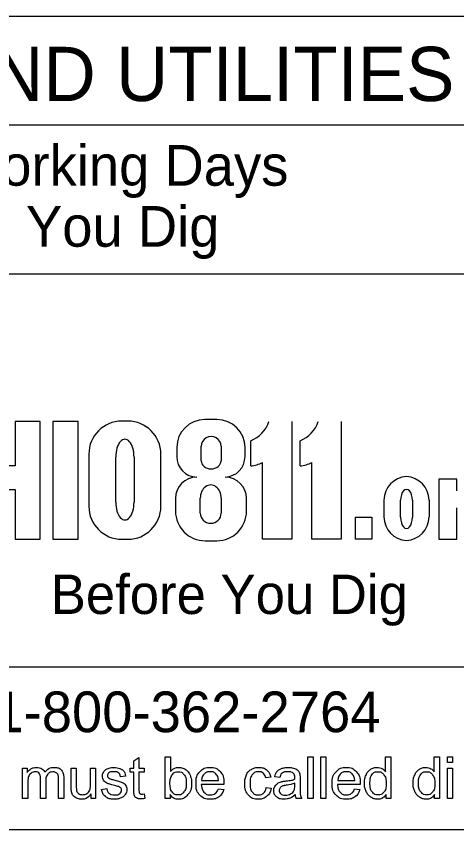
# Model space of a CAD drawing. Extents: x 421.3 to 469.3, y 221.6 to 248.2.
# Drawn here: x 426.536 to 428.323, y 223.579 to 226.879 of the extents above; entities that cross this region are included whole.
import ezdxf

# ---------------------------------------------------------------- set-up
doc = ezdxf.new("R2010")
doc.units = 0
doc.layers.add('SH_Data', color=7, linetype='Continuous')

msp = doc.modelspace()

# ---------------------------------------------------------------- linework, layer by layer
at = {"layer": 'SH_Data'}
for p, q in [((424.3328, 226.8787), (429.5577, 226.8787)), ((424.3328, 226.4387), (429.5577, 226.4387)), ((424.3328, 225.8337), (429.5577, 225.8337)), ((426.9891, 225.2364), (426.9644, 225.2364)), ((427.3503, 225.2429), (427.3014, 225.2429)), ((427.654, 225.2349), (427.654, 224.7569)), ((427.8541, 225.2349), (427.8541, 224.7569)), ((427.1874, 225.1289), (427.1874, 225.0926)), ((427.2862, 225.0756), (427.2862, 225.1343)), ((427.3671, 225.1343), (427.3671, 225.0756)), ((427.4643, 225.0926), (427.4643, 225.1289)), ((427.4873, 225.0546), (427.4873, 225.1564)), ((427.6874, 225.0546), (427.6874, 225.1564)), ((426.8308, 225.1027), (426.8308, 224.8906)), ((427.1228, 224.8906), (427.1228, 225.1027)), ((426.9397, 224.9076), (426.9397, 225.0903)), ((427.0141, 225.0903), (427.0141, 224.9076)), ((427.5356, 224.7569), (427.5356, 225.0686)), ((427.7357, 224.7569), (427.7357, 225.0686)), ((428.3228, 225.0004), (428.2498, 225.0004)), ((428.2498, 225.0004), (428.2498, 224.7569)), ((428.3228, 224.9533), (428.3228, 225.0004)), ((427.1818, 224.9225), (427.1818, 224.8717)), ((427.2827, 224.8628), (427.2827, 224.9239)), ((427.3676, 224.9239), (427.3676, 224.8628)), ((427.4703, 224.8717), (427.4703, 224.9225)), ((428.0279, 224.8478), (428.0279, 224.9156)), ((428.0951, 224.8466), (428.0951, 224.9156)), ((428.1432, 224.9156), (428.1432, 224.8466)), ((428.2104, 224.9156), (428.2104, 224.8478)), ((428.3228, 224.7569), (428.3228, 224.8843)), ((426.9644, 224.7569), (426.9891, 224.7569)), ((427.3028, 224.7507), (427.3494, 224.7507)), ((427.654, 224.7569), (427.5356, 224.7569)), ((427.8541, 224.7569), (427.7357, 224.7569)), ((428.2498, 224.7569), (428.3228, 224.7569)), ((429.5577, 224.2387), (424.3328, 224.2387)), ((429.5577, 223.5787), (424.3328, 223.5787))]:
    msp.add_line(p, q, dxfattribs=at)
for points in [[(426.4563, 224.959), (426.5324, 224.959), (426.5324, 224.7569), (426.6339, 224.7569), (426.6339, 225.2349), (426.5324, 225.2349), (426.5324, 225.0546), (426.4563, 225.0546), (426.4563, 225.2349)], [(426.6847, 224.7569), (426.7874, 224.7569), (426.7874, 225.2349), (426.6847, 225.2349), (426.6847, 224.7569)], [(427.2683, 225.009), (427.2683, 225.009)], [(427.3838, 225.009), (427.3838, 225.009)], [(427.16, 223.7055), (427.1408, 223.7055), (427.1408, 223.8749), (427.1615, 223.8749), (427.1615, 223.8146)], [(427.7192, 223.7055), (427.7192, 223.8749), (427.74, 223.8749), (427.74, 223.7055), (427.7192, 223.7055)], [(427.7717, 223.7055), (427.7717, 223.8749), (427.7925, 223.8749), (427.7925, 223.7055), (427.7717, 223.7055)], [(428.0345, 223.8142), (428.0345, 223.8749), (428.0553, 223.8749), (428.0553, 223.7055), (428.036, 223.7055)], [(428.2318, 223.8142), (428.2318, 223.8749), (428.2526, 223.8749), (428.2526, 223.7055), (428.2333, 223.7055)], [(428.2854, 223.8511), (428.2854, 223.8749), (428.3062, 223.8749), (428.3062, 223.8511), (428.2854, 223.8511)], [(427.0132, 223.7415), (427.0132, 223.8122), (426.9978, 223.8122), (426.9978, 223.8283), (427.0132, 223.8283), (427.0132, 223.8587), (427.034, 223.8712), (427.034, 223.8283), (427.0548, 223.8283), (427.0548, 223.8122), (427.034, 223.8122), (427.034, 223.7403)], [(426.5623, 223.7055), (426.5623, 223.8283), (426.5809, 223.8283), (426.5809, 223.811)], [(426.759, 223.7523), (426.759, 223.8283), (426.7797, 223.8283), (426.7797, 223.7603)], [(426.8376, 223.7626), (426.8376, 223.8283), (426.8584, 223.8283), (426.8584, 223.7055), (426.8398, 223.7055)], [(428.2854, 223.7055), (428.2854, 223.8283), (428.3062, 223.8283), (428.3062, 223.7055), (428.2854, 223.7055)], [(426.656, 223.7768), (426.656, 223.7055), (426.6352, 223.7055), (426.6352, 223.7852)], [(426.7287, 223.7898), (426.7287, 223.7055), (426.7079, 223.7055), (426.7079, 223.7828)], [(426.9801, 223.7966), (426.9597, 223.7939)], [(427.2881, 223.7786), (427.3566, 223.7786)], [(427.5684, 223.7922), (427.5481, 223.7891)], [(427.6051, 223.7905), (427.5847, 223.7932)], [(427.6874, 223.7847), (427.6874, 223.757)], [(427.8404, 223.7786), (427.909, 223.7786)], [(426.5831, 223.7692), (426.5831, 223.7055), (426.5623, 223.7055)], [(426.8827, 223.7422), (426.9032, 223.7454)], [(427.3785, 223.7616), (427.2869, 223.7616)], [(427.3564, 223.7452), (427.3779, 223.7425)], [(427.5499, 223.7505), (427.5703, 223.7478)], [(427.6664, 223.7595), (427.6665, 223.7671)], [(427.9308, 223.7616), (427.8393, 223.7616)], [(427.9088, 223.7452), (427.9302, 223.7425)], [(426.8398, 223.7055), (426.8398, 223.7237)], [(427.0548, 223.7241), (427.0577, 223.7057)], [(427.16, 223.7209), (427.16, 223.7055)], [(428.036, 223.7055), (428.036, 223.721)], [(428.2333, 223.7055), (428.2333, 223.721)], [(427.694, 223.7055), (427.6723, 223.7055)]]:
    msp.add_lwpolyline(points, dxfattribs=at)
msp.add_lwpolyline([(427.9121, 224.8466), (427.978, 224.8466), (427.978, 224.7569), (427.9121, 224.7569)], close=True, dxfattribs=at)
for centre, radius, start, end in [((426.9644, 225.1027), 0.1337, 90, 180), ((426.9891, 225.1027), 0.1337, 0, 90), ((427.3014, 225.1289), 0.114, 90, 180), ((427.3503, 225.1289), 0.114, 0, 90), ((427.4366, 225.2785), 0.1322, 292.5572, 340.7355), ((427.6367, 225.2785), 0.1322, 292.5572, 340.7355), ((427.271, 225.0926), 0.0837, 180, 268.1442), ((427.3806, 225.0926), 0.0837, 272.2058, 0), ((427.4754, 225.1862), 0.1322, 275.1733, 297.0931), ((427.6755, 225.1862), 0.1322, 275.1733, 297.0931), ((427.2683, 224.9225), 0.0865, 90, 180), ((427.3838, 224.9225), 0.0865, 0, 90), ((428.1234, 224.9156), 0.0956, 92.5886, 180), ((428.1148, 224.9156), 0.0956, 0, 87.4114), ((426.9644, 224.8906), 0.1337, 180, 270), ((426.9891, 224.8906), 0.1337, 270, 0), ((427.3028, 224.8717), 0.1209, 180, 270), ((427.3494, 224.8717), 0.1209, 270, 0), ((428.1234, 224.8478), 0.0956, 180, 267.4114), ((428.1148, 224.8478), 0.0956, 272.5886, 0)]:
    msp.add_arc(centre, radius, start, end, dxfattribs=at)
for centre, major_axis, ratio, start_param, end_param in [((426.9769, 225.0903), (0, 0.0723), 0.514403, 4.712389, 7.853982), ((427.3267, 225.1343), (0.0404, 0), 0.969373, 0, 3.141593), ((427.3267, 225.0756), (0.0404, 0), 0.818453, 3.141593, 6.283185), ((427.3251, 224.9239), (0, 0.0535), 0.794529, 4.712389, 7.853982), ((428.1192, 224.9156), (0, 0.0434), 0.553236, 4.712389, 7.853982), ((426.9769, 224.9076), (0, 0.0723), 0.514403, 1.570796, 4.712389), ((427.3251, 224.8628), (0.0425, 0), 0.959837, 3.141593, 6.283185), ((428.1192, 224.8466), (0, 0.046), 0.522014, 1.570796, 4.712389)]:
    msp.add_ellipse(centre, major_axis=major_axis, ratio=ratio, start_param=start_param, end_param=end_param, dxfattribs=at)
for points, degree in [([(426.5809, 223.811), (426.5867, 223.82), (426.5963, 223.8255), (426.6059, 223.831), (426.6181, 223.831), (426.6318, 223.831), (426.6405, 223.8254), (426.6492, 223.8197), (426.6528, 223.8095), (426.6674, 223.831), (426.6908, 223.831), (426.709, 223.831), (426.7189, 223.8209), (426.7287, 223.8108), (426.7287, 223.7898)], 3), ([(426.6352, 223.7852), (426.6352, 223.7991), (426.6302, 223.806), (426.6251, 223.813), (426.6135, 223.813), (426.6047, 223.813), (426.5972, 223.8083), (426.5898, 223.8037), (426.5864, 223.7948), (426.5831, 223.7859), (426.5831, 223.7692)], 3), ([(426.7079, 223.7828), (426.7079, 223.7953), (426.7059, 223.8008), (426.7039, 223.8063), (426.6986, 223.8096), (426.6933, 223.813), (426.6861, 223.813), (426.6731, 223.813), (426.6646, 223.8044), (426.656, 223.7958), (426.656, 223.7768)], 3), ([(426.9597, 223.7939), (426.9583, 223.8033), (426.9517, 223.8087), (426.945, 223.814), (426.9329, 223.814), (426.9185, 223.814), (426.9124, 223.8093), (426.9063, 223.8045), (426.9063, 223.7981), (426.9063, 223.7941), (426.9088, 223.7908), (426.9114, 223.7875), (426.9168, 223.7853), (426.9199, 223.7841), (426.9352, 223.78), (426.9573, 223.7741), (426.9661, 223.7703), (426.9748, 223.7666), (426.9798, 223.7594), (426.9848, 223.7523), (426.9848, 223.7416), (426.9848, 223.7312), (426.9787, 223.7221), (426.9726, 223.7129), (426.9612, 223.7079), (426.9497, 223.7028), (426.9352, 223.7028), (426.9113, 223.7028), (426.8987, 223.7128), (426.8861, 223.7227), (426.8827, 223.7422)], 3), ([(426.9032, 223.7454), (426.9049, 223.7331), (426.9129, 223.7265), (426.9208, 223.7199), (426.9351, 223.7199), (426.9494, 223.7199), (426.9564, 223.7257), (426.9633, 223.7316), (426.9633, 223.7394), (426.9633, 223.7465), (426.9572, 223.7505), (426.9529, 223.7533), (426.9359, 223.7576), (426.913, 223.7634), (426.9041, 223.7676), (426.8953, 223.7718), (426.8907, 223.7793), (426.8861, 223.7867), (426.8861, 223.7957), (426.8861, 223.8039), (426.8899, 223.8109), (426.8937, 223.8179), (426.9001, 223.8225), (426.905, 223.8261), (426.9134, 223.8286), (426.9218, 223.831), (426.9314, 223.831), (426.9459, 223.831), (426.9568, 223.8269), (426.9677, 223.8227), (426.973, 223.8156), (426.9782, 223.8085), (426.9801, 223.7966)], 3), ([(427.1597, 223.7679), (427.1597, 223.7458), (427.1657, 223.7359), (427.1755, 223.7199), (427.1923, 223.7199), (427.2059, 223.7199), (427.2158, 223.7317), (427.2257, 223.7436), (427.2257, 223.7671), (427.2257, 223.7911), (427.2162, 223.8026), (427.2067, 223.814), (427.1932, 223.814), (427.1796, 223.814), (427.1697, 223.8021), (427.1597, 223.7903), (427.1597, 223.7679)], 3), ([(427.1615, 223.8146), (427.1747, 223.831), (427.1952, 223.831), (427.2065, 223.831), (427.2166, 223.8265), (427.2267, 223.8219), (427.2332, 223.8137), (427.2398, 223.8054), (427.2434, 223.7937), (427.2471, 223.7821), (427.2471, 223.7688), (427.2471, 223.7373), (427.2315, 223.72), (427.2159, 223.7028), (427.1941, 223.7028), (427.1724, 223.7028), (427.16, 223.7209)], 3), ([(427.3779, 223.7425), (427.3728, 223.7236), (427.3591, 223.7132), (427.3453, 223.7028), (427.3239, 223.7028), (427.297, 223.7028), (427.2813, 223.7194), (427.2655, 223.736), (427.2655, 223.7659), (427.2655, 223.7969), (427.2814, 223.8139), (427.2974, 223.831), (427.3228, 223.831), (427.3474, 223.831), (427.363, 223.8143), (427.3786, 223.7975), (427.3786, 223.7671), (427.3786, 223.7653), (427.3785, 223.7616)], 3), ([(427.3566, 223.7786), (427.3552, 223.7942), (427.3488, 223.8019), (427.3388, 223.814), (427.323, 223.814), (427.3087, 223.814), (427.2989, 223.8044), (427.2891, 223.7947), (427.2881, 223.7786)], 3), ([(427.5703, 223.7478), (427.567, 223.7267), (427.5532, 223.7148), (427.5393, 223.7028), (427.5192, 223.7028), (427.494, 223.7028), (427.4787, 223.7193), (427.4634, 223.7357), (427.4634, 223.7665), (427.4634, 223.7863), (427.47, 223.8012), (427.4766, 223.8161), (427.4901, 223.8236), (427.5035, 223.831), (427.5194, 223.831), (427.5394, 223.831), (427.5521, 223.8209), (427.5648, 223.8108), (427.5684, 223.7922)], 3), ([(427.5481, 223.7891), (427.5452, 223.8015), (427.5379, 223.8077), (427.5306, 223.814), (427.5202, 223.814), (427.5045, 223.814), (427.4947, 223.8027), (427.4848, 223.7914), (427.4848, 223.7671), (427.4848, 223.7423), (427.4943, 223.7311), (427.5038, 223.7199), (427.5191, 223.7199), (427.5313, 223.7199), (427.5395, 223.7274), (427.5477, 223.7349), (427.5499, 223.7505)], 3), ([(427.6682, 223.7206), (427.6566, 223.7109), (427.6459, 223.7069), (427.6352, 223.7028), (427.623, 223.7028), (427.6028, 223.7028), (427.5919, 223.7127), (427.581, 223.7226), (427.581, 223.7379), (427.581, 223.7469), (427.5851, 223.7544), (427.5892, 223.7618), (427.5959, 223.7663), (427.6025, 223.7708), (427.6108, 223.7731), (427.617, 223.7747), (427.6293, 223.7762), (427.6545, 223.7792), (427.6664, 223.7834), (427.6665, 223.7877), (427.6665, 223.7888), (427.6665, 223.8016), (427.6606, 223.8068), (427.6527, 223.8139), (427.637, 223.8139), (427.6224, 223.8139), (427.6154, 223.8087), (427.6084, 223.8036), (427.6051, 223.7905)], 3), ([(427.5847, 223.7932), (427.5874, 223.8063), (427.5938, 223.8143), (427.6001, 223.8224), (427.6121, 223.8267), (427.6241, 223.831), (427.64, 223.831), (427.6557, 223.831), (427.6655, 223.8273), (427.6753, 223.8236), (427.6799, 223.818), (427.6845, 223.8124), (427.6864, 223.8039), (427.6874, 223.7985), (427.6874, 223.7847)], 3), ([(427.9302, 223.7425), (427.9252, 223.7236), (427.9114, 223.7132), (427.8977, 223.7028), (427.8763, 223.7028), (427.8494, 223.7028), (427.8336, 223.7194), (427.8178, 223.736), (427.8178, 223.7659), (427.8178, 223.7969), (427.8338, 223.8139), (427.8497, 223.831), (427.8751, 223.831), (427.8997, 223.831), (427.9153, 223.8143), (427.9309, 223.7975), (427.9309, 223.7671), (427.9309, 223.7653), (427.9308, 223.7616)], 3), ([(427.909, 223.7786), (427.9076, 223.7942), (427.9011, 223.8019), (427.8912, 223.814), (427.8753, 223.814), (427.861, 223.814), (427.8512, 223.8044), (427.8415, 223.7947), (427.8404, 223.7786)], 3), ([(428.036, 223.721), (428.0244, 223.7028), (428.0017, 223.7028), (427.987, 223.7028), (427.9747, 223.7109), (427.9624, 223.719), (427.9557, 223.7335), (427.9489, 223.748), (427.9489, 223.7668), (427.9489, 223.7852), (427.955, 223.8001), (427.9611, 223.8151), (427.9733, 223.8231), (427.9856, 223.831), (428.0007, 223.831), (428.0118, 223.831), (428.0204, 223.8264), (428.0291, 223.8217), (428.0345, 223.8142)], 3), ([(427.9703, 223.7668), (427.9703, 223.7432), (427.9803, 223.7315), (427.9902, 223.7199), (428.0037, 223.7199), (428.0174, 223.7199), (428.0269, 223.731), (428.0364, 223.7422), (428.0364, 223.7651), (428.0364, 223.7903), (428.0267, 223.8021), (428.017, 223.8139), (428.0028, 223.8139), (427.9889, 223.8139), (427.9796, 223.8025), (427.9703, 223.7912), (427.9703, 223.7668)], 3), ([(428.2333, 223.721), (428.2217, 223.7028), (428.199, 223.7028), (428.1843, 223.7028), (428.172, 223.7109), (428.1597, 223.719), (428.1529, 223.7335), (428.1462, 223.748), (428.1462, 223.7668), (428.1462, 223.7852), (428.1523, 223.8001), (428.1584, 223.8151), (428.1706, 223.8231), (428.1829, 223.831), (428.198, 223.831), (428.2091, 223.831), (428.2177, 223.8264), (428.2264, 223.8217), (428.2318, 223.8142)], 3), ([(428.1676, 223.7668), (428.1676, 223.7432), (428.1776, 223.7315), (428.1875, 223.7199), (428.201, 223.7199), (428.2147, 223.7199), (428.2242, 223.731), (428.2337, 223.7422), (428.2337, 223.7651), (428.2337, 223.7903), (428.224, 223.8021), (428.2143, 223.8139), (428.2001, 223.8139), (428.1862, 223.8139), (428.1769, 223.8025), (428.1676, 223.7912), (428.1676, 223.7668)], 3), ([(426.8398, 223.7237), (426.8255, 223.7028), (426.8009, 223.7028), (426.79, 223.7028), (426.7806, 223.707), (426.7712, 223.7111), (426.7666, 223.7174), (426.7621, 223.7237), (426.7602, 223.7329), (426.759, 223.739), (426.759, 223.7523)], 3), ([(426.7797, 223.7603), (426.7797, 223.744), (426.781, 223.7383), (426.783, 223.7301), (426.7893, 223.7255), (426.7957, 223.7208), (426.805, 223.7208), (426.8144, 223.7208), (426.8226, 223.7256), (426.8308, 223.7304), (426.8342, 223.7386), (426.8376, 223.7469), (426.8376, 223.7626)], 3), ([(427.0577, 223.7057), (427.049, 223.7039), (427.042, 223.7039), (427.0307, 223.7039), (427.0245, 223.7075), (427.0183, 223.711), (427.0157, 223.7169), (427.0132, 223.7227), (427.0132, 223.7415)], 3), ([(427.2869, 223.7616), (427.2881, 223.7414), (427.2984, 223.7306), (427.3087, 223.7199), (427.324, 223.7199), (427.3355, 223.7199), (427.3436, 223.7259), (427.3517, 223.7319), (427.3564, 223.7452)], 3), ([(427.6665, 223.7671), (427.6552, 223.7625), (427.6325, 223.7593), (427.6197, 223.7574), (427.6144, 223.7551), (427.609, 223.7528), (427.6061, 223.7484), (427.6032, 223.7439), (427.6032, 223.7385), (427.6032, 223.7302), (427.6095, 223.7246), (427.6158, 223.7191), (427.628, 223.7191), (427.64, 223.7191), (427.6493, 223.7244), (427.6587, 223.7296), (427.6631, 223.7387), (427.6664, 223.7458), (427.6664, 223.7595)], 3), ([(427.6874, 223.757), (427.6874, 223.728), (427.6888, 223.7203), (427.6901, 223.7126), (427.694, 223.7055)], 3), ([(427.8393, 223.7616), (427.8404, 223.7414), (427.8507, 223.7306), (427.861, 223.7199), (427.8764, 223.7199), (427.8878, 223.7199), (427.8959, 223.7259), (427.904, 223.7319), (427.9088, 223.7452)], 3), ([(427.034, 223.7403), (427.034, 223.7313), (427.0351, 223.7288), (427.0362, 223.7262), (427.0386, 223.7247), (427.0411, 223.7232), (427.0457, 223.7232), (427.0491, 223.7232), (427.0548, 223.7241)], 3), ([(427.6723, 223.7055), (427.6691, 223.712), (427.6682, 223.7206)], 2)]:
    msp.add_open_spline(points, degree=degree, dxfattribs=at)

# ---------------------------------------------------------------- texts
for s, height, p in [('UNDERGROUND UTILITIES', 0.22, (424.5053, 226.5347)), ('Contact Two Working Days', 0.165, (424.9672, 226.1913)), ('Before You Dig', 0.165, (425.8643, 225.9438)), ('Before You Dig', 0.15972, (426.6762, 224.4539)), ('OHIO811, 8-1-1, or 1-800-362-2764', 0.165, (424.4938, 223.9744))]:
    msp.add_text(s, height=height, dxfattribs=at).set_placement(p)

doc.saveas('drawing.dxf')
